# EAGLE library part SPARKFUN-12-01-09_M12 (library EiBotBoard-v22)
Header 12 Standard 12-pin 0.1" header. Use with straight break away headers (SKU : PRT-00116), right angle break away headers (PRT-00553), swiss pins (PRT-00743), machine pins (PRT-00117), and female headers (PRT-00115).
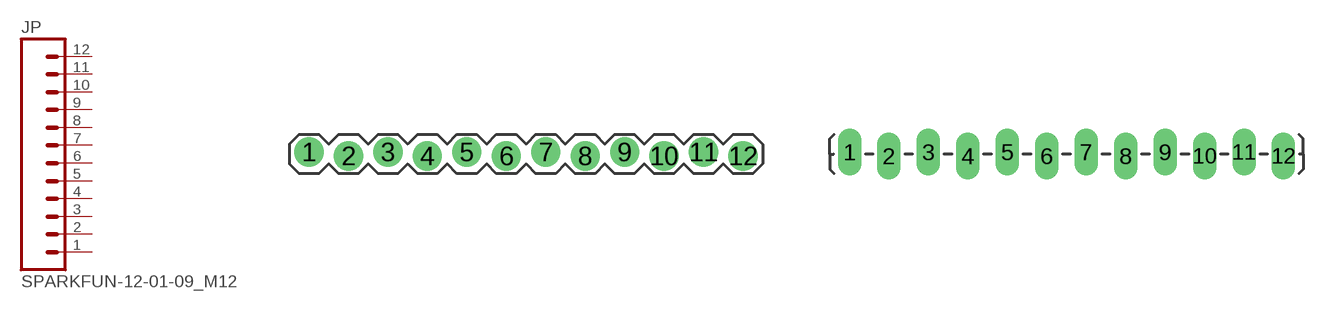
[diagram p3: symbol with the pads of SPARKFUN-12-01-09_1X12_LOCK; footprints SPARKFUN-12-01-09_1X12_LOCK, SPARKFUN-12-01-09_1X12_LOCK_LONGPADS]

Designator prefix JP

## SPARKFUN-12-01-09_M12LOCK  [SPARKFUN-12-01-09_1X12_LOCK]
1  1  pas
2  2  pas
3  3  pas
4  4  pas
5  5  pas
6  6  pas
7  7  pas
8  8  pas
9  9  pas
10  10  pas
11  11  pas
12  12  pas

## SPARKFUN-12-01-09_M12LOCK_LONGPADS  [SPARKFUN-12-01-09_1X12_LOCK_LONGPADS]
Pads as for SPARKFUN-12-01-09_1X12_LOCK

## SPARKFUN-12-01-09_M12MACHINE-PIN_LOCK  [SPARKFUN-12-01-09_1X12_MACHINE-PIN-HEADER_LOCK.004]
Pads as for SPARKFUN-12-01-09_1X12_LOCK

## SPARKFUN-12-01-09_M12PTH  [SPARKFUN-12-01-09_1X12]
Pads as for SPARKFUN-12-01-09_1X12_LOCK

## Footprint SPARKFUN-12-01-09_1X12_LOCK (pad centres in mm)
drill 1.016 pad 1.88 round: 1 0,0.127; 2 2.54,-0.127; 3 5.08,0.127; 4 7.62,-0.127; 5 10.16,0.127; 6 12.7,-0.127; 7 15.24,0.127; 8 17.78,-0.127; 9 20.32,0.127; 10 22.86,-0.127; 11 25.4,0.127; 12 27.94,-0.127

## Footprint SPARKFUN-12-01-09_1X12_LOCK_LONGPADS (pad centres in mm)
drill 1.016 long: 1 0,0.127; 2 2.54,-0.127; 3 5.08,0.127; 4 7.62,-0.127; 5 10.16,0.127; 6 12.7,-0.127; 7 15.24,0.127; 8 17.78,-0.127; 9 20.32,0.127; 10 22.86,-0.127; 11 25.4,0.127; 12 27.94,-0.127

## Footprint SPARKFUN-12-01-09_1X12_MACHINE-PIN-HEADER_LOCK.004 (pad centres in mm)
drill 0.889 pad 1.88 round: 1 0,0.102; 2 2.54,-0.102; 3 5.08,0.102; 4 7.62,-0.102; 5 10.16,0.102; 6 12.7,-0.102; 7 15.24,0.102; 8 17.78,-0.102; 9 20.32,0.102; 10 22.86,-0.102; 11 25.4,0.102; 12 27.94,-0.102

## Footprint SPARKFUN-12-01-09_1X12 (pad centres in mm)
drill 1.016 pad 1.88 round: 1 0,0; 2 2.54,0; 3 5.08,0; 4 7.62,0; 5 10.16,0; 6 12.7,0; 7 15.24,0; 8 17.78,0; 9 20.32,0; 10 22.86,0; 11 25.4,0; 12 27.94,0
